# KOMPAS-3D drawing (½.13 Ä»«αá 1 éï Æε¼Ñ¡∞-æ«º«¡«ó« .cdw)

Views: Вид 1, Вид 2
Referenced files: Подвеска ВЧ-заградителя.cdw
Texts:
  Текст на чертеже
  Размерные надписи
  Шероховатость
  Линия-выноска #1
  Линия-выноска #2
  Линия-выноска #3
  Отклонения формы и база
  Заголовок таблицы
  Ячейка таблицы
  Стрелка вида
  Обозначение изменения
  Фигурная скобка
  Номер узла
  Марка координационной оси
  VRCB
  Выносная надпись
  Обозначение узла
  Марка/позиционное обозначение с линией-выноской
  Марка/позиционное обозначение на линии
  Марка/позиционное обозначение без линии-выноски
  ООббыыччнныыйй
  Definition Term
  Definition List
  Address
  Blockquote
  Preformatted
  Courier New
  z-Bottom of Form
  z-Top of Form
  Лит-Масса-Масштаб
  Материал-Предприятие
  Title Specification
  Body Specification ( left align )
  Body Specificaton ( centered )
  Без имени
  SPEC
  Normal
  Txt
  Body Text
  heading 1
  Знак Знак Знак Знак Знак Знак
  Verdana
  Simplex
  TXT
  txt
  MS Sans Serif
  Additional DXF text style 0
  Обычный
  Термин
  Список определений
  Адрес
  Цитаты
  Форматированный
  Z-конец формы
  Z-начало формы
  ТекстШаг1
  Title
  Денис
  header
  heading 2
  AGOpus
  footer
  NormalParagraphStyle
  Body Text 3
  ссылки
  Подпись в квадратике
  табл
  цепи
  Маркировка
  клеммы, контакты
  тексты табл
  Тексты. 3,2
  ЗОНА_привяз
  текст переноса
  ТТееррммиинн
  ССппииссоокк ооппррееддееллеенниийй
  ААддрреесс
  ЦЦииттааттыы
  ФФооррммааттиирроовваанннныыйй
  Z-ккооннеецц ффооррммыы
  Z-ннааччааллоо ффооррммыы
  GOST 2.304 type A
  rustxt
  heading 8
  heading 3
  heading 6
  heading 7
  russ
  Абзац Знак
  heading 4
  heading 5
  heading 9
  HeliosLight
  Pa3
  Pa1
  Три с половиной
  style2
  Шрифт 2.5
  Заголовки
  RUSTXT
  Table Contents
  Table Heading
  ГОСТ_МНЕ
  ESK - Обозначение
  маркировка
  ISOCP
  ROMANS
  SIMPLEX
  Обычный (веб)
  Текст 3,5
  Tahoma
  CNBNDG+TimesNewRoman
  Subtitle
  ISOCPEUR
  FR5
  romans
  Подписи
  Схема монтажа ВЧ-заградителя на опору №1.
  Отпайка ВЛ-110 кВ Тюмень-Сазоново на ПС Каскара
  Примечание - примечания см. 16/01-ПОС, л.10.
  Кран КС-35719-1-02
  CONTINUOUS_RGB_0_0_0_THICK_0.13
  GOST2.303 4_RGB_0_0_0_SC_0.04_THICK_0.13
  CONTINUOUS_RGB_0_0_0_THICK_0.18
  CONTINUOUS_RGB_173_173_173_THICK_0.13
  GOST2.303 4_RGB_173_173_173_SC_0.04_THICK_0.13
  СONTINUOUS_RGB_0_0_0_THICK_0.13
  POLYLINE_STYLE_0.30_RGB_0_0_0
  CONTINUOUS_RGB_0_0_0_THICK_0.3
  GOST2.303 6_RGB_0_0_0_SC_0.04_THICK_0.13
  POLYLINE_STYLE_0.18_RGB_0_0_0
  GOST2.303 6_RGB_0_0_0_SC_0_THICK_0.18
  K5LT_AXLED_RGB_255_128_0_SC_1_THICK_0.18
  CONTINUOUS_RGB_0_0_0_THICK_0.25
  POLYLINE_STYLE_0.21_RGB_0_0_0
  СONTINUOUS_RGB_0_0_0_THICK_0.18
  POLYLINE_STYLE_0.50_RGB_0_0_0
  POLYLINE_STYLE_0.40_RGB_0_0_0
  CONTINUOUS_RGB_0_0_0_THICK_0.6
  Стили документа
  Автомобильный кран КС-35714
  Ромин
  Подвеска ВЧ-заградителя
  на опоре №1
  Политова
  Разраб.
  Микрюков
  Схема пневматическая соединений
  Перезавод ВЛ на ПС Тюмень. Реконструкция устройств
  РЗ и ПА на обратных концах отходящих ВЛ,
  ВОЛС Тюменского ТПО
  ВЛ 110 кВ Тюмень - Созоново
  Нов.
  ГИП
  Матвеев
Dimensions and other numbers on the sheet: 16/01-ПОС; 7; 3,2_; 3.5; 2.5; 2,5; 1,8; 3,2; 2,5 (контакты, клеммы); 3,2 (надписи); 3,2 (Зоны); 5; 2,5_01; 2,5_3; 3,5_01; 3,5_tabl; 5_заголовок; 2,3_; 3,2_зона не привяз; 3,5; 3.2 маркировка; 3,2 элементы; 3,2 линия; 3,2 таблица; 2,5 грязносинь; 2.5 курсив; 2.5_Э5_надписи; 2.5_Э5_ссылки; 2.5_кабель; 3.2; 2.5 надписи; 3 и 5; 5,0_белый_подчёркнутый; 3.2 фиол; 3.2 (текст); 12; 4; 05.14; 16/01-03-091-ЭП-; 13; 3; 253-14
